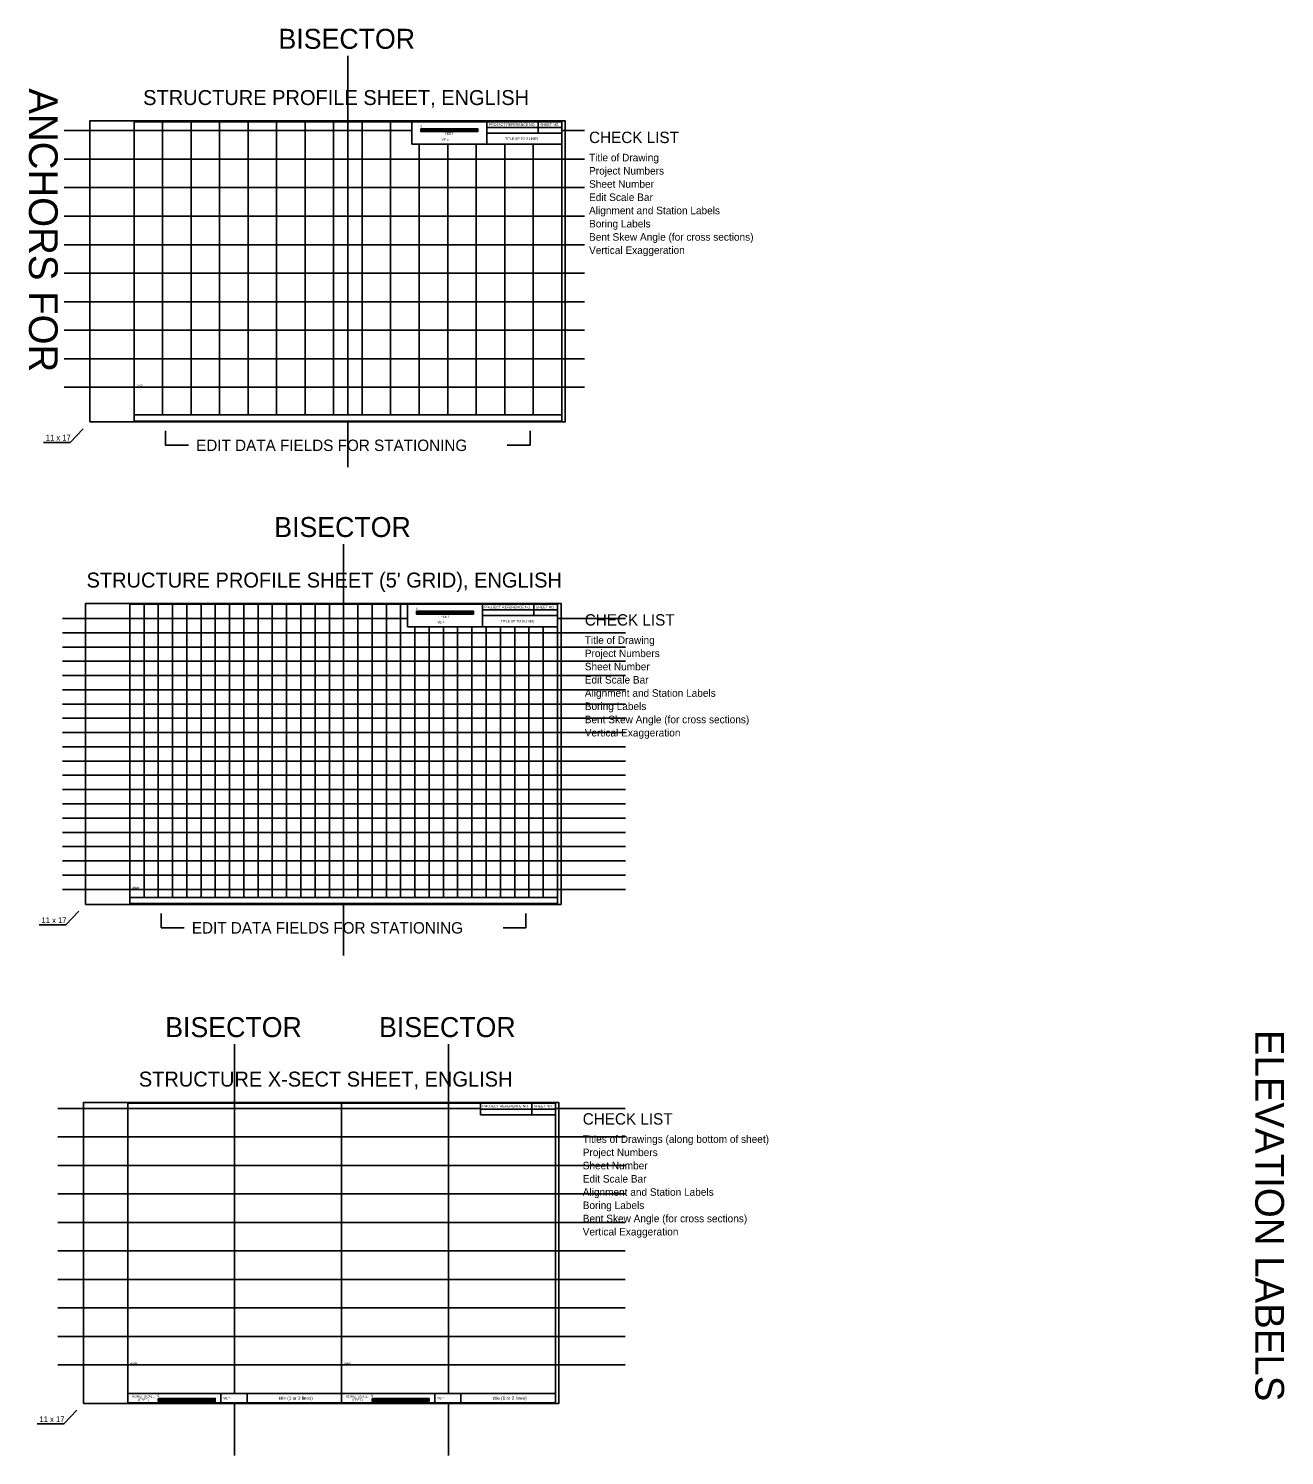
# Model space of a CAD drawing. Extents: x 278618 to 280654, y 171155 to 171855.
# Drawn here: x 279543 to 279983, y 171156 to 171657 of the extents above; entities that cross this region are included whole.
import ezdxf

# ---------------------------------------------------------------- set-up
doc = ezdxf.new("R2010")
doc.units = 0
for name, color, linetype in [('Geotech Sheets and Borders Cell', 7, 'Continuous'), ('Prop Strc Sect_ Grid - minor', 7, 'Continuous'), ('Prop Strc Sect_ Misc - Drafting Aid (dashed line)', 7, 'Continuous'), ('Prop Strc Sect_ Misc - User Comment (Tx - small)', 7, 'Continuous'), ('Scratch_Level_0', 7, 'Continuous'), ('Scratch_Level_2', 7, 'Continuous'), ('Scratch_Level_4', 7, 'Continuous'), ('Sheet Dot Grid CELL', 7, 'Continuous'), ('Sheet Plot Border Inside CELL', 7, 'Continuous')]:
    doc.layers.add(name, color=color, linetype=linetype)

msp = doc.modelspace()

# ---------------------------------------------------------------- linework, layer by layer
at = {"layer": 'Geotech Sheets and Borders Cell'}
for p, q in [((279721.61, 171624.09), (279721.61, 171620.09)), ((279703.6, 171622.09), (279729.9, 171622.09)), ((279579.9, 171521.24), (279729.9, 171521.24)), ((279702.1, 171452.85), (279728.4, 171452.85)), ((279720.12, 171454.85), (279720.12, 171450.85)), ((279578.4, 171352), (279728.4, 171352)), ((279652.68, 171279.81), (279652.68, 171174.81)), ((279701.38, 171277.81), (279727.68, 171277.81)), ((279719.39, 171279.81), (279719.39, 171275.81)), ((279610.34, 171178.01), (279610.34, 171174.81)), ((279610.34, 171178.01), (279610.34, 171174.81)), ((279619.57, 171178.01), (279619.57, 171174.81)), ((279685.34, 171178.01), (279685.34, 171174.81)), ((279694.57, 171178.01), (279694.57, 171174.81))]:
    msp.add_line(p, q, dxfattribs=at)
for points in [[(279579.9, 171624.09), (279729.9, 171624.09), (279729.9, 171519.09), (279579.9, 171519.09)], [(279677.3, 171616.19), (279729.9, 171616.19), (279729.9, 171624.09), (279677.3, 171624.09)], [(279703.6, 171620.09), (279729.9, 171620.09), (279729.9, 171624.09), (279703.6, 171624.09)], [(279703.6, 171624.09), (279729.9, 171624.09), (279729.9, 171616.19), (279703.6, 171616.19)], [(279680.45, 171621.62), (279700.45, 171621.62), (279700.45, 171620.62), (279680.45, 171620.62)], [(279680.45, 171621.62), (279690.45, 171621.62), (279690.45, 171621.12), (279680.45, 171621.12)], [(279690.45, 171621.12), (279700.45, 171621.12), (279700.45, 171620.62), (279690.45, 171620.62)], [(279578.4, 171454.85), (279728.4, 171454.85), (279728.4, 171349.85), (279578.4, 171349.85)], [(279675.81, 171446.95), (279728.4, 171446.95), (279728.4, 171454.85), (279675.81, 171454.85)], [(279678.96, 171452.38), (279698.96, 171452.38), (279698.96, 171451.38), (279678.96, 171451.38)], [(279678.96, 171452.38), (279688.96, 171452.38), (279688.96, 171451.88), (279678.96, 171451.88)], [(279702.1, 171454.85), (279728.4, 171454.85), (279728.4, 171446.95), (279702.1, 171446.95)], [(279702.1, 171450.85), (279728.4, 171450.85), (279728.4, 171454.85), (279702.1, 171454.85)], [(279688.96, 171451.88), (279698.96, 171451.88), (279698.96, 171451.38), (279688.96, 171451.38)], [(279577.68, 171279.81), (279727.68, 171279.81), (279727.68, 171174.81), (279577.68, 171174.81)], [(279701.38, 171275.81), (279727.68, 171275.81), (279727.68, 171279.81), (279701.38, 171279.81)], [(279577.68, 171178.01), (279652.68, 171178.01), (279652.68, 171174.81), (279577.68, 171174.81)], [(279652.68, 171178.01), (279727.68, 171178.01), (279727.68, 171174.81), (279652.68, 171174.81)], [(279588.36, 171176.3), (279608.36, 171176.3), (279608.36, 171175.3), (279588.36, 171175.3)], [(279588.36, 171176.3), (279598.36, 171176.3), (279598.36, 171175.8), (279588.36, 171175.8)], [(279598.36, 171175.8), (279608.36, 171175.8), (279608.36, 171175.3), (279598.36, 171175.3)], [(279663.36, 171176.3), (279683.36, 171176.3), (279683.36, 171175.3), (279663.36, 171175.3)], [(279663.36, 171176.3), (279673.36, 171176.3), (279673.36, 171175.8), (279663.36, 171175.8)], [(279673.36, 171175.8), (279683.36, 171175.8), (279683.36, 171175.3), (279673.36, 171175.3)]]:
    msp.add_lwpolyline(points, close=True, dxfattribs=at)
at = {"layer": 'Prop Strc Sect_ Grid - minor'}
for p, q in [((279589.9, 171521.24), (279589.9, 171624.09)), ((279599.9, 171521.24), (279599.9, 171624.09)), ((279609.9, 171521.24), (279609.9, 171624.09)), ((279619.9, 171521.24), (279619.9, 171624.09)), ((279629.9, 171521.24), (279629.9, 171624.09)), ((279639.9, 171521.24), (279639.9, 171624.09)), ((279649.9, 171521.24), (279649.9, 171624.09)), ((279659.9, 171521.24), (279659.9, 171624.09)), ((279669.9, 171521.24), (279669.9, 171624.09)), ((279677.3, 171620.97), (279579.9, 171620.97)), ((279679.9, 171521.24), (279679.9, 171616.19)), ((279689.9, 171521.24), (279689.9, 171616.19)), ((279699.9, 171521.24), (279699.9, 171616.19)), ((279709.9, 171521.24), (279709.9, 171616.19)), ((279719.9, 171521.24), (279719.9, 171616.19)), ((279729.9, 171610.97), (279579.9, 171610.97)), ((279729.9, 171600.97), (279579.9, 171600.97)), ((279729.9, 171590.97), (279579.9, 171590.97)), ((279729.9, 171580.97), (279579.9, 171580.97)), ((279729.9, 171570.97), (279579.9, 171570.97)), ((279729.9, 171560.97), (279579.9, 171560.97)), ((279729.9, 171550.97), (279579.9, 171550.97)), ((279729.9, 171540.97), (279579.9, 171540.97)), ((279729.9, 171530.97), (279579.9, 171530.97)), ((279652.68, 171278.03), (279577.68, 171278.03)), ((279701.38, 171278.03), (279652.68, 171278.03)), ((279652.68, 171268.03), (279577.68, 171268.03)), ((279727.68, 171268.03), (279652.68, 171268.03)), ((279652.68, 171258.03), (279577.68, 171258.03)), ((279727.68, 171258.03), (279652.68, 171258.03)), ((279652.68, 171248.03), (279577.68, 171248.03)), ((279727.68, 171248.03), (279652.68, 171248.03)), ((279652.68, 171238.03), (279577.68, 171238.03)), ((279727.68, 171238.03), (279652.68, 171238.03)), ((279652.68, 171228.03), (279577.68, 171228.03)), ((279727.68, 171228.03), (279652.68, 171228.03)), ((279652.68, 171218.03), (279577.68, 171218.03)), ((279727.68, 171218.03), (279652.68, 171218.03)), ((279652.68, 171208.03), (279577.68, 171208.03)), ((279727.68, 171208.03), (279652.68, 171208.03)), ((279652.68, 171198.03), (279577.68, 171198.03)), ((279727.68, 171198.03), (279652.68, 171198.03)), ((279652.68, 171188.03), (279577.68, 171188.03)), ((279727.68, 171188.03), (279652.68, 171188.03))]:
    msp.add_line(p, q, dxfattribs=at)
at = {"layer": 'Prop Strc Sect_ Misc - Drafting Aid (dashed line)'}
for p, q in [((279654.9, 171647.19), (279654.9, 171521.24)), ((279581.06, 171620.97), (279555.37, 171620.97)), ((279737.89, 171620.97), (279729.9, 171620.97)), ((279581.06, 171610.97), (279555.37, 171610.97)), ((279737.89, 171610.97), (279728.74, 171610.97)), ((279581.06, 171600.97), (279555.37, 171600.97)), ((279737.89, 171600.97), (279728.74, 171600.97)), ((279581.06, 171590.97), (279555.37, 171590.97)), ((279737.89, 171590.97), (279728.74, 171590.97)), ((279581.06, 171580.97), (279555.37, 171580.97)), ((279737.89, 171580.97), (279728.74, 171580.97)), ((279581.06, 171570.97), (279555.37, 171570.97)), ((279737.89, 171570.97), (279728.74, 171570.97)), ((279581.06, 171560.97), (279555.37, 171560.97)), ((279737.89, 171560.97), (279728.74, 171560.97)), ((279581.06, 171550.97), (279555.37, 171550.97)), ((279737.89, 171550.97), (279728.74, 171550.97)), ((279581.06, 171540.97), (279555.37, 171540.97)), ((279737.89, 171540.97), (279728.74, 171540.97)), ((279581.06, 171530.97), (279555.37, 171530.97)), ((279737.89, 171530.97), (279728.74, 171530.97)), ((279654.9, 171519.09), (279654.9, 171502.94)), ((279653.4, 171475.95), (279653.4, 171352)), ((279580.43, 171449.85), (279554.75, 171449.85)), ((279728.4, 171449.85), (279752.23, 171449.85)), ((279580.43, 171444.85), (279554.75, 171444.85)), ((279726.54, 171444.85), (279752.23, 171444.85)), ((279580.43, 171439.85), (279554.75, 171439.85)), ((279726.54, 171439.85), (279752.23, 171439.85)), ((279580.43, 171434.85), (279554.75, 171434.85)), ((279726.54, 171434.85), (279752.23, 171434.85)), ((279580.43, 171429.85), (279554.75, 171429.85)), ((279726.54, 171429.85), (279752.23, 171429.85)), ((279580.43, 171424.85), (279554.75, 171424.85)), ((279726.54, 171424.85), (279752.23, 171424.85)), ((279580.43, 171419.85), (279554.75, 171419.85)), ((279726.54, 171419.85), (279752.23, 171419.85)), ((279580.43, 171414.85), (279554.75, 171414.85)), ((279726.54, 171414.85), (279752.23, 171414.85)), ((279580.43, 171409.85), (279554.75, 171409.85)), ((279726.54, 171409.85), (279752.23, 171409.85)), ((279580.43, 171404.85), (279554.75, 171404.85)), ((279726.54, 171404.85), (279752.23, 171404.85)), ((279580.43, 171399.85), (279554.75, 171399.85)), ((279726.54, 171399.85), (279752.23, 171399.85)), ((279580.43, 171394.85), (279554.75, 171394.85)), ((279726.54, 171394.85), (279752.23, 171394.85)), ((279580.43, 171389.85), (279554.75, 171389.85)), ((279726.54, 171389.85), (279752.23, 171389.85)), ((279580.43, 171384.85), (279554.75, 171384.85)), ((279726.54, 171384.85), (279752.23, 171384.85)), ((279580.43, 171379.85), (279554.75, 171379.85)), ((279726.54, 171379.85), (279752.23, 171379.85)), ((279580.43, 171374.85), (279554.75, 171374.85)), ((279726.54, 171374.85), (279752.23, 171374.85)), ((279580.43, 171369.85), (279554.75, 171369.85)), ((279726.54, 171369.85), (279752.23, 171369.85)), ((279580.43, 171364.85), (279554.75, 171364.85)), ((279726.54, 171364.85), (279752.23, 171364.85)), ((279580.43, 171359.85), (279554.75, 171359.85)), ((279726.54, 171359.85), (279752.23, 171359.85)), ((279580.43, 171354.85), (279554.75, 171354.85)), ((279726.54, 171354.85), (279752.23, 171354.85)), ((279653.4, 171349.85), (279653.4, 171331.69)), ((279615.18, 171300.55), (279615.18, 171178.01)), ((279690.18, 171300.55), (279690.18, 171178.01)), ((279553.15, 171278.03), (279578.84, 171278.03)), ((279650.58, 171278.03), (279640.68, 171278.03)), ((279654.77, 171278.03), (279664.68, 171278.03)), ((279752.2, 171278.03), (279727.68, 171278.03)), ((279553.15, 171268.03), (279578.84, 171268.03)), ((279650.58, 171268.03), (279640.68, 171268.03)), ((279654.77, 171268.03), (279664.68, 171268.03)), ((279752.2, 171268.03), (279726.52, 171268.03)), ((279553.15, 171258.03), (279578.84, 171258.03)), ((279650.58, 171258.03), (279640.68, 171258.03)), ((279654.77, 171258.03), (279664.68, 171258.03)), ((279752.2, 171258.03), (279726.52, 171258.03)), ((279553.15, 171248.03), (279578.84, 171248.03)), ((279650.58, 171248.03), (279640.68, 171248.03)), ((279654.77, 171248.03), (279664.68, 171248.03)), ((279752.2, 171248.03), (279726.52, 171248.03)), ((279553.15, 171238.03), (279578.84, 171238.03)), ((279650.58, 171238.03), (279640.68, 171238.03)), ((279654.77, 171238.03), (279664.68, 171238.03)), ((279752.2, 171238.03), (279726.52, 171238.03)), ((279553.15, 171228.03), (279578.84, 171228.03)), ((279650.58, 171228.03), (279640.68, 171228.03)), ((279654.77, 171228.03), (279664.68, 171228.03)), ((279752.2, 171228.03), (279726.52, 171228.03)), ((279553.15, 171218.03), (279578.84, 171218.03)), ((279650.58, 171218.03), (279640.68, 171218.03)), ((279654.77, 171218.03), (279664.68, 171218.03)), ((279752.2, 171218.03), (279726.52, 171218.03)), ((279553.15, 171208.03), (279578.84, 171208.03)), ((279650.58, 171208.03), (279640.68, 171208.03)), ((279654.77, 171208.03), (279664.68, 171208.03)), ((279752.2, 171208.03), (279726.52, 171208.03)), ((279553.15, 171198.03), (279578.84, 171198.03)), ((279650.58, 171198.03), (279640.68, 171198.03)), ((279654.77, 171198.03), (279664.68, 171198.03)), ((279752.2, 171198.03), (279726.52, 171198.03)), ((279553.15, 171188.03), (279578.84, 171188.03)), ((279650.58, 171188.03), (279640.68, 171188.03)), ((279654.77, 171188.03), (279664.68, 171188.03)), ((279752.2, 171188.03), (279726.52, 171188.03)), ((279615.18, 171174.81), (279615.18, 171156.29)), ((279690.18, 171174.81), (279690.18, 171156.29))]:
    msp.add_line(p, q, dxfattribs=at)
at = {"layer": 'Scratch_Level_0'}
for p, q in [((279731.15, 171624.37), (279731.15, 171624.37)), ((279564.38, 171518.8), (279564.38, 171518.8)), ((279729.65, 171455.13), (279729.65, 171455.13)), ((279562.89, 171349.56), (279562.89, 171349.56)), ((279728.93, 171280.09), (279728.93, 171280.09)), ((279562.16, 171174.53), (279562.16, 171174.53))]:
    msp.add_line(p, q, dxfattribs=at)
for points in [[(279548.11, 171511.61), (279557.5, 171511.61), (279562.09, 171516.41)], [(279546.62, 171342.37), (279556, 171342.37), (279560.59, 171347.17)], [(279545.9, 171167.33), (279555.28, 171167.33), (279559.87, 171172.13)]]:
    msp.add_lwpolyline(points, dxfattribs=at)
at = {"layer": 'Scratch_Level_4'}
for points in [[(279598.99, 171510.6), (279590.96, 171510.6), (279590.96, 171515.68)], [(279710.8, 171510.6), (279718.83, 171510.6), (279718.83, 171515.68)], [(279597.49, 171341.36), (279589.47, 171341.36), (279589.47, 171346.43)], [(279709.31, 171341.36), (279717.34, 171341.36), (279717.34, 171346.43)]]:
    msp.add_lwpolyline(points, dxfattribs=at)
at = {"layer": 'Sheet Dot Grid CELL'}
for p, q in [((279583.4, 171454.85), (279583.4, 171352)), ((279588.4, 171454.85), (279588.4, 171352)), ((279593.4, 171454.85), (279593.4, 171352)), ((279598.4, 171454.85), (279598.4, 171352)), ((279603.4, 171454.85), (279603.4, 171352)), ((279608.4, 171454.85), (279608.4, 171352)), ((279613.4, 171454.85), (279613.4, 171352)), ((279618.4, 171454.85), (279618.4, 171352)), ((279623.4, 171454.85), (279623.4, 171352)), ((279628.4, 171454.85), (279628.4, 171352)), ((279633.4, 171454.85), (279633.4, 171352)), ((279638.4, 171454.85), (279638.4, 171352)), ((279643.4, 171454.85), (279643.4, 171352)), ((279648.4, 171454.85), (279648.4, 171352)), ((279653.4, 171454.85), (279653.4, 171352)), ((279658.4, 171454.85), (279658.4, 171352)), ((279663.4, 171454.85), (279663.4, 171352)), ((279668.4, 171454.85), (279668.4, 171352)), ((279673.4, 171454.85), (279673.4, 171352)), ((279578.4, 171449.85), (279675.81, 171449.85)), ((279578.4, 171444.85), (279728.4, 171444.85)), ((279678.4, 171446.95), (279678.4, 171352)), ((279683.4, 171446.95), (279683.4, 171352)), ((279688.4, 171446.95), (279688.4, 171352)), ((279693.4, 171446.95), (279693.4, 171352)), ((279698.4, 171446.95), (279698.4, 171352)), ((279703.4, 171446.95), (279703.4, 171352)), ((279708.4, 171446.95), (279708.4, 171352)), ((279713.4, 171446.95), (279713.4, 171352)), ((279718.4, 171446.95), (279718.4, 171352)), ((279723.4, 171446.95), (279723.4, 171352)), ((279578.4, 171439.85), (279728.4, 171439.85)), ((279578.4, 171434.85), (279728.4, 171434.85)), ((279578.4, 171429.85), (279728.4, 171429.85)), ((279578.4, 171424.85), (279728.4, 171424.85)), ((279578.4, 171419.85), (279728.4, 171419.85)), ((279578.4, 171414.85), (279728.4, 171414.85)), ((279578.4, 171409.85), (279728.4, 171409.85)), ((279578.4, 171404.85), (279728.4, 171404.85)), ((279578.4, 171399.85), (279728.4, 171399.85)), ((279578.4, 171394.85), (279728.4, 171394.85)), ((279578.4, 171389.85), (279728.4, 171389.85)), ((279578.4, 171384.85), (279728.4, 171384.85)), ((279578.4, 171379.85), (279728.4, 171379.85)), ((279578.4, 171374.85), (279728.4, 171374.85)), ((279578.4, 171369.85), (279728.4, 171369.85)), ((279578.4, 171364.85), (279728.4, 171364.85)), ((279578.4, 171359.85), (279728.4, 171359.85)), ((279578.4, 171354.85), (279728.4, 171354.85))]:
    msp.add_line(p, q, dxfattribs=at)
at = {"layer": 'Sheet Plot Border Inside CELL'}
for points in [[(279564.38, 171518.8), (279731.15, 171518.8), (279731.15, 171624.37), (279564.38, 171624.37)], [(279562.89, 171349.56), (279729.65, 171349.56), (279729.65, 171455.13), (279562.89, 171455.13)], [(279562.16, 171174.53), (279728.93, 171174.53), (279728.93, 171280.09), (279562.16, 171280.09)]]:
    msp.add_lwpolyline(points, close=True, dxfattribs=at)

# ---------------------------------------------------------------- texts
at = {"layer": 'Geotech Sheets and Borders Cell'}
for s, height, p in [('0', 0.84, (279680.21, 171622.1)), ('PROJECT REFERENCE NO.', 0.9, (279704.31, 171622.64)), ('SHEET NO.', 0.9, (279722.32, 171622.64)), ('VE =  ', 0.84, (279687.74, 171617.4)), ('FEET', 0.84, (279688.9, 171619.41)), ('###', 1.001, (279580.79, 171530.97)), ('0', 0.84, (279678.72, 171452.86)), ('PROJECT REFERENCE NO.', 0.9, (279702.82, 171453.4)), ('SHEET NO.', 0.9, (279720.83, 171453.4)), ('VE =  ', 0.84, (279686.25, 171448.16)), ('FEET', 0.84, (279687.41, 171450.17)), ('###', 1.008, (279579.31, 171354.85)), ('PROJECT REFERENCE NO.', 0.9, (279702.09, 171278.36)), ('SHEET NO.', 0.9, (279720.1, 171278.36)), ('###', 1.001, (279578.58, 171188.03)), ('###', 1.001, (279653.58, 171188.03)), ('HORIZ. SCALE', 0.84, (279579.12, 171176.59)), ('0', 0.84, (279588.12, 171176.78)), ('HORIZ. SCALE', 0.84, (279654.12, 171176.59)), ('0', 0.84, (279663.12, 171176.78)), ('(FEET)', 0.84, (279581.33, 171175.35)), ('VE =  ', 0.84, (279611.19, 171175.97)), ('title (1 or 2 lines) ', 1.1681, (279630.67, 171175.81)), ('(FEET)', 0.84, (279656.33, 171175.35)), ('VE =  ', 0.84, (279686.19, 171175.97)), ('title (1 or 2 lines) ', 1.1681, (279705.67, 171175.81))]:
    msp.add_text(s, height=height, dxfattribs=at).set_placement(p)
for p in [(279710.02, 171617.74), (279708.53, 171448.5)]:
    msp.add_text('TITLE UP TO 3 LINES', height=0.84, rotation=360, dxfattribs=at).set_placement(p)
at = {"layer": 'Prop Strc Sect_ Misc - User Comment (Tx - small)'}
for p in [(279630.55, 171649.67), (279629.06, 171478.43), (279590.83, 171303.03), (279665.83, 171303.03)]:
    msp.add_text('BISECTOR', height=7.009, dxfattribs=at).set_placement(p)
for s, p in [('ANCHORS FOR', (279543.04, 171635.81)), ('ELEVATION LABELS', (279973.16, 171305.58))]:
    msp.add_text(s, height=10.0769, rotation=270, dxfattribs=at).set_placement(p)
at = {"layer": 'Scratch_Level_0'}
for p in [(279548.93, 171512.28), (279547.44, 171343.04), (279546.71, 171168)]:
    msp.add_text('11 x 17', height=2, dxfattribs=at).set_placement(p)
at = {"layer": 'Scratch_Level_2'}
for s, p in [('STRUCTURE PROFILE SHEET, ENGLISH', (279583.09, 171629.95)), ("STRUCTURE PROFILE SHEET (5' GRID), ENGLISH", (279563.24, 171460.71)), ('STRUCTURE X-SECT SHEET, ENGLISH', (279581.57, 171285.67))]:
    msp.add_text(s, height=5.25, dxfattribs=at).set_placement(p)
at = {"layer": 'Scratch_Level_4'}
for s, height, p in [('CHECK LIST', 4, (279739.49, 171616.61)), ('Title of Drawing', 2.64, (279739.49, 171610.21)), ('Project Numbers', 2.64, (279739.49, 171605.57)), ('Sheet Number', 2.64, (279739.49, 171600.93)), ('Edit Scale Bar', 2.64, (279739.49, 171596.29)), ('Alignment and Station Labels', 2.64, (279739.49, 171591.65)), ('Boring Labels', 2.64, (279739.49, 171587.01)), ('Bent Skew Angle (for cross sections)', 2.64, (279739.49, 171582.37)), ('Vertical Exaggeration', 2.64, (279739.49, 171577.73)), ('EDIT DATA FIELDS FOR STATIONING', 4, (279601.67, 171508.6)), ('CHECK LIST', 4, (279737.99, 171447.37)), ('Title of Drawing', 2.64, (279737.99, 171440.96)), ('Project Numbers', 2.64, (279737.99, 171436.32)), ('Sheet Number', 2.64, (279737.99, 171431.68)), ('Edit Scale Bar', 2.64, (279737.99, 171427.04)), ('Alignment and Station Labels', 2.64, (279737.99, 171422.4)), ('Boring Labels', 2.64, (279737.99, 171417.76)), ('Bent Skew Angle (for cross sections)', 2.64, (279737.99, 171413.12)), ('Vertical Exaggeration', 2.64, (279737.99, 171408.48)), ('EDIT DATA FIELDS FOR STATIONING', 4, (279600.17, 171339.36)), ('CHECK LIST', 4, (279737.27, 171272.33)), ('Titles of Drawings (along bottom of sheet)', 2.64, (279737.27, 171265.93)), ('Project Numbers', 2.64, (279737.27, 171261.29)), ('Sheet Number', 2.64, (279737.27, 171256.65)), ('Edit Scale Bar', 2.64, (279737.27, 171252.01)), ('Alignment and Station Labels', 2.64, (279737.27, 171247.37)), ('Boring Labels', 2.64, (279737.27, 171242.73)), ('Bent Skew Angle (for cross sections)', 2.64, (279737.27, 171238.09)), ('Vertical Exaggeration', 2.64, (279737.27, 171233.45))]:
    msp.add_text(s, height=height, dxfattribs=at).set_placement(p)

doc.saveas('drawing.dxf')
